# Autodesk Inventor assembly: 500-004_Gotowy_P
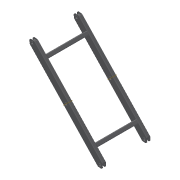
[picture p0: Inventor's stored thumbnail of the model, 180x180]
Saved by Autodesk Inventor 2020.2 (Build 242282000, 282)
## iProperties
Created: 2016-09
Part Number: 500-004_Gotowy_P
Document SubType Name: Assembly
Designer: F.Stasiak
Description: Ramię podwójne
Manager: www.cadconsulting.pl
Company: Fabian Stasiak CAD Consulting
Author: F.Stasiak
Subject: Zbiór ćwiczeń. Autodesk Inventor 2020. Kurs podstawowy
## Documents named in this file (4)
- C:\2020_Kurs_podstawowy\R6 Zespoły\Warsztat\Komponenty\500-004_Gotowy_P.iam
- C:\2020_Kurs_podstawowy\R6 Zespoły\Warsztat\Komponenty\DIN 59 410 - 500-03-04.ipt
- C:\2020_Kurs_podstawowy\R6 Zespoły\Warsztat\Komponenty\500-03-02.ipt
- C:\2020_Kurs_podstawowy\R6 Zespoły\Warsztat\Komponenty\DIN 59 410 - 500-03-03.ipt
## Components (10 placed, 3 different names)
1. DIN 59 410 - 500-03-04:1
2. DIN 59 410 - 500-03-04:2
3. 500-03-02:1
4. 500-03-02:2
5. 500-03-02:3
6. 500-03-02:4
7. 500-03-02:5
8. 500-03-02:6
9. DIN 59 410 - 500-03-03:1
10. DIN 59 410 - 500-03-03:2
